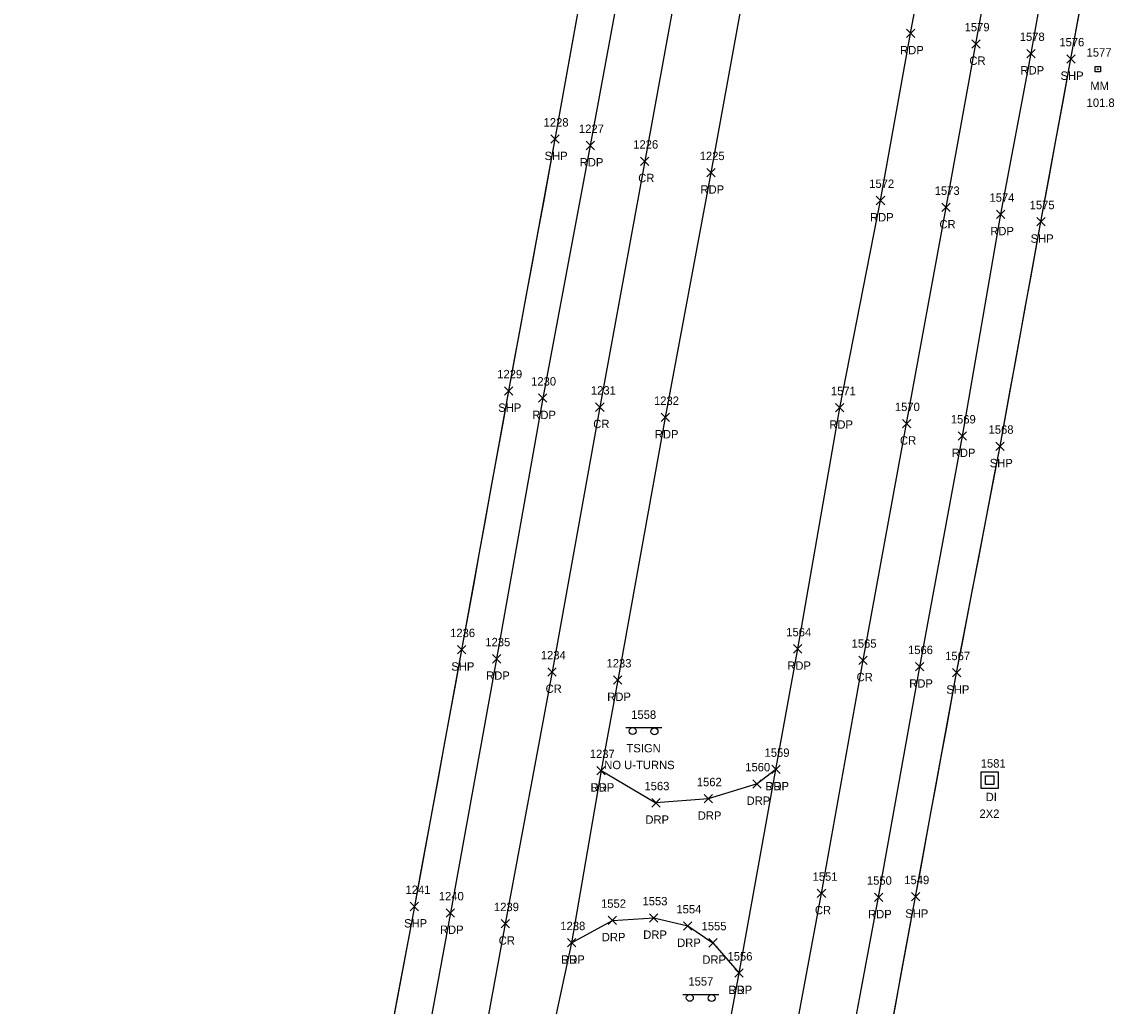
# Model space of a CAD drawing. Extents: x 1472022 to 1479249, y 777216 to 786527.
# Drawn here: x 1473646.9 to 1473907.5, y 780347.1 to 780581.9 of the extents above; entities that cross this region are included whole.
import ezdxf

# ---------------------------------------------------------------- set-up
doc = ezdxf.new("R2010")
doc.units = 0
for name, color, linetype in [('D_A', 7, 'Continuous'), ('D_C', 7, 'Continuous'), ('D_I', 7, 'Continuous'), ('DS', 7, 'Continuous'), ('LSOGP', 7, 'Continuous'), ('P_A', 7, 'Continuous'), ('P_I', 7, 'Continuous'), ('P_TIC', 7, 'Continuous'), ('PET', 7, 'Continuous'), ('PRC', 7, 'Continuous'), ('PSP', 7, 'Continuous'), ('R_A', 7, 'Continuous'), ('R_I', 7, 'Continuous'), ('R_TIC', 7, 'Continuous'), ('RDP', 7, 'Continuous'), ('S_A', 7, 'Continuous'), ('S_C', 7, 'Continuous'), ('S_I', 7, 'Continuous'), ('SRM', 7, 'Continuous'), ('SSGN', 7, 'Continuous')]:
    doc.layers.add(name, color=color, linetype=linetype)

msp = doc.modelspace()

# ---------------------------------------------------------------- linework, layer by layer
at = {"layer": 'DS'}
for p, q in [((1473875.82, 780403), (1473879.82, 780403)), ((1473875.82, 780399), (1473875.82, 780403)), ((1473876.82, 780400), (1473876.82, 780402)), ((1473876.82, 780402), (1473878.82, 780402)), ((1473877.83, 780401), (1473877.83, 780401)), ((1473877.83, 780401), (1473877.83, 780401)), ((1473878.82, 780402), (1473878.82, 780400)), ((1473879.82, 780403), (1473879.82, 780399)), ((1473879.82, 780399), (1473875.82, 780399)), ((1473878.82, 780400), (1473876.82, 780400))]:
    msp.add_line(p, q, dxfattribs=at)
at = {"layer": 'LSOGP'}
for points in [[(1473779.79, 780585.68), (1473778.37, 780577.73), (1473776.94, 780569.79), (1473775.52, 780561.85), (1473774.09, 780553.9), (1473772.71, 780546.4), (1473771.33, 780538.89), (1473769.95, 780531.38), (1473768.56, 780523.88), (1473767.18, 780516.37), (1473765.8, 780508.86), (1473764.41, 780501.36), (1473763.03, 780493.85), (1473761.63, 780486.13), (1473760.23, 780478.42), (1473758.83, 780470.7), (1473757.43, 780462.98), (1473756.03, 780455.27), (1473754.63, 780447.55), (1473753.24, 780439.83), (1473751.84, 780432.12), (1473750.43, 780424.46), (1473749.02, 780416.81), (1473747.61, 780409.15), (1473746.21, 780401.5), (1473744.8, 780393.84), (1473743.39, 780386.18), (1473741.98, 780378.53), (1473740.58, 780370.87), (1473739, 780362.47), (1473737.42, 780354.07), (1473735.84, 780345.67)], [(1473854.21, 780341.14), (1473855.4, 780347.56), (1473856.58, 780353.97), (1473857.77, 780360.38), (1473858.96, 780366.79), (1473860.15, 780373.2), (1473861.37, 780379.88), (1473862.6, 780386.56), (1473863.82, 780393.24), (1473865.05, 780399.91), (1473866.28, 780406.59), (1473867.5, 780413.27), (1473868.73, 780419.95), (1473869.95, 780426.63), (1473871.25, 780433.38), (1473872.54, 780440.13), (1473873.84, 780446.88), (1473875.13, 780453.63), (1473876.43, 780460.38), (1473877.72, 780467.13), (1473879.02, 780473.88), (1473880.31, 780480.63), (1473881.53, 780487.32), (1473882.75, 780494.01), (1473883.97, 780500.71), (1473885.19, 780507.4), (1473886.41, 780514.1), (1473887.63, 780520.79), (1473888.84, 780527.48), (1473890.06, 780534.18), (1473891.85, 780543.89), (1473893.64, 780553.6), (1473895.42, 780563.32), (1473897.21, 780573.03), (1473898.23, 780578.62), (1473899.25, 780584.21)]]:
    msp.add_lwpolyline(points, dxfattribs=at)
at = {"layer": 'P_TIC'}
for points in [[(1473857.97, 780578.12), (1473859.97, 780580.12)], [(1473859.97, 780578.12), (1473857.97, 780580.12)], [(1473873.56, 780575.61), (1473875.56, 780577.61)], [(1473875.56, 780575.61), (1473873.56, 780577.61)], [(1473886.71, 780573.3), (1473888.71, 780575.3)], [(1473888.71, 780573.3), (1473886.71, 780575.3)], [(1473896.21, 780572.03), (1473898.21, 780574.03)], [(1473898.21, 780572.03), (1473896.21, 780574.03)], [(1473773.09, 780552.9), (1473775.09, 780554.9)], [(1473775.09, 780552.9), (1473773.09, 780554.9)], [(1473781.52, 780551.37), (1473783.52, 780553.37)], [(1473783.52, 780551.37), (1473781.52, 780553.37)], [(1473794.53, 780547.63), (1473796.53, 780549.63)], [(1473796.53, 780547.63), (1473794.53, 780549.63)], [(1473810.33, 780544.89), (1473812.33, 780546.89)], [(1473812.33, 780544.89), (1473810.33, 780546.89)], [(1473850.78, 780538.26), (1473852.78, 780540.26)], [(1473852.78, 780538.26), (1473850.78, 780540.26)], [(1473866.42, 780536.6), (1473868.42, 780538.6)], [(1473868.42, 780536.6), (1473866.42, 780538.6)], [(1473879.48, 780534.96), (1473881.48, 780536.96)], [(1473881.48, 780534.96), (1473879.48, 780536.96)], [(1473889.06, 780533.18), (1473891.06, 780535.18)], [(1473891.06, 780533.18), (1473889.06, 780535.18)], [(1473762.03, 780492.85), (1473764.03, 780494.85)], [(1473764.03, 780492.85), (1473762.03, 780494.85)], [(1473770.2, 780491.12), (1473772.2, 780493.12)], [(1473772.2, 780491.12), (1473770.2, 780493.12)], [(1473783.81, 780488.97), (1473785.81, 780490.97)], [(1473785.81, 780488.97), (1473783.81, 780490.97)], [(1473841.07, 780488.82), (1473843.07, 780490.82)], [(1473843.07, 780488.82), (1473841.07, 780490.82)], [(1473799.44, 780486.51), (1473801.44, 780488.51)], [(1473801.44, 780486.51), (1473799.44, 780488.51)], [(1473857, 780485.03), (1473859, 780487.03)], [(1473859, 780485.03), (1473857, 780487.03)], [(1473870.31, 780482.08), (1473872.31, 780484.08)], [(1473872.31, 780482.08), (1473870.31, 780484.08)], [(1473879.31, 780479.63), (1473881.31, 780481.63)], [(1473881.31, 780479.63), (1473879.31, 780481.63)], [(1473750.84, 780431.12), (1473752.84, 780433.12)], [(1473752.84, 780431.12), (1473750.84, 780433.12)], [(1473831.05, 780431.32), (1473833.05, 780433.32)], [(1473833.05, 780431.32), (1473831.05, 780433.32)], [(1473759.19, 780428.94), (1473761.19, 780430.94)], [(1473761.19, 780428.94), (1473759.19, 780430.94)], [(1473846.63, 780428.6), (1473848.63, 780430.6)], [(1473848.63, 780428.6), (1473846.63, 780430.6)], [(1473772.42, 780425.81), (1473774.42, 780427.81)], [(1473774.42, 780425.81), (1473772.42, 780427.81)], [(1473860.15, 780427.07), (1473862.15, 780429.07)], [(1473862.15, 780427.07), (1473860.15, 780429.07)], [(1473868.95, 780425.63), (1473870.95, 780427.63)], [(1473870.95, 780425.63), (1473868.95, 780427.63)], [(1473788.09, 780423.89), (1473790.09, 780425.89)], [(1473790.09, 780423.89), (1473788.09, 780425.89)], [(1473784.11, 780402.28), (1473786.11, 780404.28)], [(1473786.11, 780402.28), (1473784.11, 780404.28)], [(1473825.83, 780402.57), (1473827.83, 780404.57)], [(1473827.83, 780402.57), (1473825.83, 780404.57)], [(1473836.7, 780373.01), (1473838.7, 780375.01)], [(1473838.7, 780373.01), (1473836.7, 780375.01)], [(1473850.32, 780372.06), (1473852.32, 780374.06)], [(1473852.32, 780372.06), (1473850.32, 780374.06)], [(1473859.15, 780372.2), (1473861.15, 780374.2)], [(1473861.15, 780372.2), (1473859.15, 780374.2)], [(1473739.58, 780369.87), (1473741.58, 780371.87)], [(1473741.58, 780369.87), (1473739.58, 780371.87)], [(1473748.17, 780368.33), (1473750.17, 780370.33)], [(1473750.17, 780368.33), (1473748.17, 780370.33)], [(1473761.25, 780365.77), (1473763.25, 780367.77)], [(1473763.25, 780365.77), (1473761.25, 780367.77)], [(1473777.08, 780361.23), (1473779.08, 780363.23)], [(1473779.08, 780361.23), (1473777.08, 780363.23)], [(1473817.03, 780353.99), (1473819.03, 780355.99)], [(1473819.03, 780353.99), (1473817.03, 780355.99)]]:
    msp.add_lwpolyline(points, dxfattribs=at)
at = {"layer": 'PET'}
for points in [[(1473746.48, 779804.23), (1473735, 779806.45), (1473719.43, 779809.21), (1473722.68, 779826.96), (1473722.64, 779829.09), (1473731.65, 779877.71), (1473741.4, 779933.53), (1473746.83, 779966.3), (1473755, 780011.96), (1473766.14, 780070.64), (1473776.66, 780127.43), (1473786.78, 780182.03), (1473796.49, 780236.66), (1473805.8, 780286.73), (1473813.14, 780328.66), (1473818.03, 780354.99), (1473826.83, 780403.57), (1473832.05, 780432.32), (1473842.07, 780489.82), (1473851.78, 780539.26), (1473858.97, 780579.12), (1473867.36, 780624.13)], [(1473748.73, 779803.86), (1473746.48, 779804.23), (1473749.84, 779823.79), (1473758.54, 779869.63), (1473769.57, 779928.11), (1473775.61, 779960.49), (1473783.9, 780007.6), (1473794.95, 780065.64), (1473805.21, 780123.07), (1473815.24, 780176.97), (1473825.12, 780231.74), (1473834.38, 780281.06), (1473842, 780323.35), (1473851.32, 780373.06), (1473861.15, 780428.07), (1473871.31, 780483.08), (1473880.48, 780535.96), (1473887.71, 780574.3), (1473895.6, 780618.75)], [(1473794.13, 780615.24), (1473782.52, 780552.37), (1473771.2, 780492.12), (1473760.19, 780429.94), (1473749.17, 780369.33), (1473737.05, 780303.75), (1473725.28, 780241.43), (1473714.85, 780182.67), (1473704.33, 780127.35), (1473693.08, 780062.48), (1473683.1, 780008.62), (1473673.01, 779953.25), (1473663.96, 779903.08), (1473652.83, 779841.01), (1473649.09, 779823)], [(1473823.42, 780612.39), (1473811.33, 780545.89), (1473800.44, 780487.51), (1473789.09, 780424.89), (1473785.11, 780403.28), (1473778.08, 780362.23), (1473770.89, 780328.95), (1473766.97, 780298.8), (1473754.95, 780235.54), (1473743.53, 780174.64), (1473733.79, 780120.94), (1473722.51, 780060.44), (1473711.99, 780003.09), (1473701.81, 779948.07), (1473692.05, 779897.36), (1473680.21, 779836.9), (1473679.29, 779834.87), (1473676.24, 779818.18), (1473663.54, 779820.45), (1473649.09, 779823)]]:
    msp.add_lwpolyline(points, dxfattribs=at)
at = {"layer": 'PRC'}
for points in [[(1473735, 779806.45), (1473738.41, 779825.86), (1473746.88, 779873.78), (1473757.16, 779931.4), (1473763.53, 779963.46), (1473771.55, 780009.55), (1473781.83, 780068.07), (1473792.3, 780125.59), (1473802.3, 780178.66), (1473811.81, 780233.39), (1473821.47, 780283.6), (1473828.72, 780325.68), (1473837.7, 780374.01), (1473847.63, 780429.6), (1473858, 780486.03), (1473867.42, 780537.6), (1473874.56, 780576.61), (1473882.64, 780621.02)], [(1473807.59, 780614.57), (1473795.53, 780548.63), (1473784.81, 780489.97), (1473773.42, 780426.81), (1473762.25, 780366.77), (1473750.55, 780303.15), (1473738.69, 780240.19), (1473727.91, 780180.81), (1473717.59, 780123.6), (1473707.02, 780064.19), (1473696.41, 780006.24), (1473686.64, 779951.22), (1473677.2, 779900.33), (1473668.24, 779851.14), (1473663.54, 779820.45)]]:
    msp.add_lwpolyline(points, dxfattribs=at)
at = {"layer": 'PSP'}
for points in [[(1473785.49, 780617.45), (1473774.09, 780553.9), (1473763.03, 780493.85), (1473751.84, 780432.12), (1473740.58, 780370.87), (1473727.95, 780303.67), (1473717.24, 780242.77), (1473706.31, 780183.74), (1473696.11, 780128.97), (1473684.01, 780064.22), (1473674.48, 780009.55), (1473665.57, 779955.55), (1473658.15, 779904.32), (1473649.83, 779842.42), (1473650, 779841.1), (1473646.9, 779823.47)], [(1473748.73, 779803.86), (1473752.42, 779823.56), (1473762.71, 779868.4), (1473775.32, 779926.92), (1473782.16, 779958.6), (1473792.83, 780005.65), (1473803.68, 780063.67), (1473813.75, 780121.6), (1473823.74, 780173.97), (1473833.9, 780230.35), (1473842.97, 780280.28), (1473850.64, 780321.91), (1473860.15, 780373.2), (1473869.95, 780426.63), (1473880.31, 780480.63), (1473890.06, 780534.18), (1473897.21, 780573.03), (1473905.39, 780617.74)]]:
    msp.add_lwpolyline(points, dxfattribs=at)
at = {"layer": 'R_TIC'}
for points in [[(1473784.11, 780402.28), (1473786.11, 780404.28)], [(1473786.11, 780402.28), (1473784.11, 780404.28)], [(1473825.83, 780402.57), (1473827.83, 780404.57)], [(1473827.83, 780402.57), (1473825.83, 780404.57)], [(1473821.34, 780399.11), (1473823.34, 780401.11)], [(1473823.34, 780399.11), (1473821.34, 780401.11)], [(1473797.2, 780394.6), (1473799.2, 780396.6)], [(1473799.2, 780394.6), (1473797.2, 780396.6)], [(1473797.2, 780394.6), (1473799.2, 780396.6)], [(1473799.2, 780394.6), (1473797.2, 780396.6)], [(1473809.69, 780395.56), (1473811.69, 780397.56)], [(1473811.69, 780395.56), (1473809.69, 780397.56)], [(1473786.8, 780366.57), (1473788.8, 780368.57)], [(1473788.8, 780366.57), (1473786.8, 780368.57)], [(1473796.69, 780367.15), (1473798.69, 780369.15)], [(1473798.69, 780367.15), (1473796.69, 780369.15)], [(1473804.77, 780365.23), (1473806.77, 780367.23)], [(1473806.77, 780365.23), (1473804.77, 780367.23)], [(1473777.08, 780361.23), (1473779.08, 780363.23)], [(1473779.08, 780361.23), (1473777.08, 780363.23)], [(1473810.78, 780361.2), (1473812.78, 780363.2)], [(1473812.78, 780361.2), (1473810.78, 780363.2)], [(1473817.03, 780353.99), (1473819.03, 780355.99)], [(1473819.03, 780353.99), (1473817.03, 780355.99)]]:
    msp.add_lwpolyline(points, dxfattribs=at)
at = {"layer": 'RDP'}
for points in [[(1473785.11, 780403.28), (1473798.2, 780395.6)], [(1473826.83, 780403.57), (1473822.34, 780400.11), (1473810.69, 780396.56), (1473798.2, 780395.6)], [(1473778.08, 780362.23), (1473787.8, 780367.57), (1473797.69, 780368.15), (1473805.77, 780366.23), (1473811.78, 780362.2), (1473818.03, 780354.99)]]:
    msp.add_lwpolyline(points, dxfattribs=at)
at = {"layer": 'SRM'}
msp.add_lwpolyline([(1473903.02, 780571.2), (1473904.27, 780571.2), (1473904.27, 780569.95), (1473903.02, 780569.95)], close=True, dxfattribs=at)
msp.add_circle((1473903.65, 780570.58), 0.0833, dxfattribs=at)
at = {"layer": 'SSGN'}
for p, q in [((1473790.98, 780413.55), (1473799.57, 780413.55)), ((1473795, 780412.64), (1473795, 780412.64)), ((1473804.62, 780349.92), (1473813.22, 780349.92)), ((1473808.64, 780349.02), (1473808.64, 780349.02))]:
    msp.add_line(p, q, dxfattribs=at)
for centre in [(1473792.64, 780412.71), (1473797.85, 780412.64), (1473806.28, 780349.09), (1473811.5, 780349.02)]:
    msp.add_circle(centre, 0.833, dxfattribs=at)

# ---------------------------------------------------------------- texts
at = {"layer": 'D_A'}
msp.add_text('DI', height=2, dxfattribs=at).set_placement((1473876.88, 780396))
at = {"layer": 'D_C'}
msp.add_text('2X2', height=2, dxfattribs=at).set_placement((1473875.4, 780392))
at = {"layer": 'D_I'}
msp.add_text('1581', height=2, dxfattribs=at).set_placement((1473875.7, 780404))
at = {"layer": 'P_A'}
for s, p in [('RDP', (1473856.45, 780574.12)), ('CR', (1473873, 780571.61)), ('RDP', (1473885.19, 780569.3)), ('SHP', (1473894.74, 780568.03)), ('SHP', (1473771.63, 780548.9)), ('RDP', (1473780.01, 780547.37)), ('CR', (1473793.97, 780543.63)), ('RDP', (1473808.82, 780540.89)), ('RDP', (1473849.27, 780534.26)), ('CR', (1473865.85, 780532.6)), ('RDP', (1473877.97, 780530.96)), ('SHP', (1473887.6, 780529.18)), ('SHP', (1473760.57, 780488.85)), ('RDP', (1473768.69, 780487.12)), ('CR', (1473783.24, 780484.97)), ('RDP', (1473839.56, 780484.82)), ('RDP', (1473797.93, 780482.51)), ('CR', (1473856.43, 780481.03)), ('RDP', (1473868.79, 780478.08)), ('SHP', (1473877.85, 780475.63)), ('RDP', (1473829.53, 780427.32)), ('SHP', (1473749.37, 780427.12)), ('RDP', (1473757.68, 780424.94)), ('CR', (1473846.07, 780424.6)), ('RDP', (1473858.64, 780423.07)), ('CR', (1473771.86, 780421.81)), ('RDP', (1473786.58, 780419.89)), ('SHP', (1473867.49, 780421.63)), ('RDP', (1473824.31, 780398.57)), ('RDP', (1473782.6, 780398.28)), ('CR', (1473836.13, 780369.01)), ('RDP', (1473848.81, 780368.06)), ('SHP', (1473857.68, 780368.2)), ('SHP', (1473738.11, 780365.87)), ('RDP', (1473746.66, 780364.33)), ('CR', (1473760.69, 780361.77)), ('RDP', (1473775.57, 780357.23)), ('RDP', (1473815.52, 780349.99))]:
    msp.add_text(s, height=2, dxfattribs=at).set_placement(p)
at = {"layer": 'P_I'}
for s, p in [('1579', (1473871.86, 780579.61)), ('1578', (1473885.01, 780577.3)), ('1576', (1473894.46, 780576.03)), ('1228', (1473771.4, 780556.9)), ('1227', (1473779.83, 780555.37)), ('1226', (1473792.78, 780551.63)), ('1225', (1473808.64, 780548.89)), ('1572', (1473849.09, 780542.26)), ('1573', (1473864.72, 780540.6)), ('1574', (1473877.79, 780538.96)), ('1575', (1473887.37, 780537.18)), ('1229', (1473760.33, 780496.85)), ('1230', (1473768.42, 780495.12)), ('1231', (1473782.68, 780492.97)), ('1571', (1473839.95, 780492.82)), ('1232', (1473797.74, 780490.51)), ('1570', (1473855.22, 780489.03)), ('1569', (1473868.56, 780486.08)), ('1568', (1473877.57, 780483.63)), ('1236', (1473749.09, 780435.12)), ('1564', (1473829.3, 780435.32)), ('1235', (1473757.49, 780432.94)), ('1565', (1473844.89, 780432.6)), ('1234', (1473770.73, 780429.81)), ('1566', (1473858.35, 780431.07)), ('1233', (1473786.4, 780427.89)), ('1567', (1473867.21, 780429.63)), ('1559', (1473824.12, 780406.57)), ('1237', (1473782.41, 780406.28)), ('1551', (1473835.57, 780377.01)), ('1550', (1473848.54, 780376.06)), ('1549', (1473857.45, 780376.2)), ('1241', (1473738.45, 780373.87)), ('1240', (1473746.39, 780372.33)), ('1239', (1473759.55, 780369.77)), ('1238', (1473775.39, 780365.23)), ('1556', (1473815.28, 780357.99))]:
    msp.add_text(s, height=2, dxfattribs=at).set_placement(p)
at = {"layer": 'R_A'}
for p in [(1473824.31, 780398.57), (1473782.6, 780398.28), (1473819.83, 780395.11), (1473808.18, 780391.56), (1473795.68, 780390.6), (1473795.68, 780390.6), (1473785.28, 780362.57), (1473795.17, 780363.15), (1473803.26, 780361.23), (1473775.57, 780357.23), (1473809.27, 780357.2), (1473815.52, 780349.99)]:
    msp.add_text('DRP', height=2, dxfattribs=at).set_placement(p)
at = {"layer": 'R_I'}
for s, p in [('1559', (1473824.12, 780406.57)), ('1237', (1473782.41, 780406.28)), ('1560', (1473819.51, 780403.11)), ('1563', (1473795.46, 780398.6)), ('1563', (1473795.46, 780398.6)), ('1562', (1473807.95, 780399.56)), ('1552', (1473785.1, 780370.57)), ('1553', (1473794.99, 780371.15)), ('1554', (1473803.08, 780369.23)), ('1238', (1473775.39, 780365.23)), ('1555', (1473809.09, 780365.2)), ('1556', (1473815.28, 780357.99))]:
    msp.add_text(s, height=2, dxfattribs=at).set_placement(p)
at = {"layer": 'S_A'}
for s, p in [('MM', (1473901.84, 780565.58)), ('TSIGN', (1473791.17, 780407.63))]:
    msp.add_text(s, height=2, dxfattribs=at).set_placement(p)
at = {"layer": 'S_C'}
for s, p in [('101.8', (1473900.96, 780561.58)), ('NO U-TURNS', (1473785.87, 780403.63))]:
    msp.add_text(s, height=2, dxfattribs=at).set_placement(p)
at = {"layer": 'S_I'}
for s, p in [('1577', (1473900.96, 780573.58)), ('1558', (1473792.3, 780415.63)), ('1557', (1473805.94, 780352))]:
    msp.add_text(s, height=2, dxfattribs=at).set_placement(p)

doc.saveas('drawing.dxf')
